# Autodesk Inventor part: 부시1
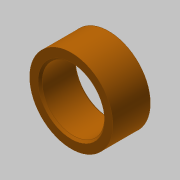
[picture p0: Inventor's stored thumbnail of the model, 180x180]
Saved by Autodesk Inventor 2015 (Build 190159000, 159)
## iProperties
Created: 2016-08
Part Number: 부시1
Material: 강철, 탄소
Document SubType Name: Modeling
Designer: mduedu
Density: 7.87 g/cm^3
Appearance: 주황색
Author: mduedu
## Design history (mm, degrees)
sketch "스케치1"
  geometry: C1 r 7.5 at (0, 0); C2 r 10 at (0, 0); 1 further point
  constraints: 2 centre point, 2 coincident
  dimensions: "d0" = 15 diameter of C1; "d1" = 20 diameter of C2
extrude "돌출1" new body sketch "스케치1" stored distance "d2" = 9; taper "d3" = 0 deg
chamfer "모따기1" distance "d4" = 0.5; stored, may be unused: second distance "d5" = 2, angle "d6" = 45 deg
node "솔리드1"
